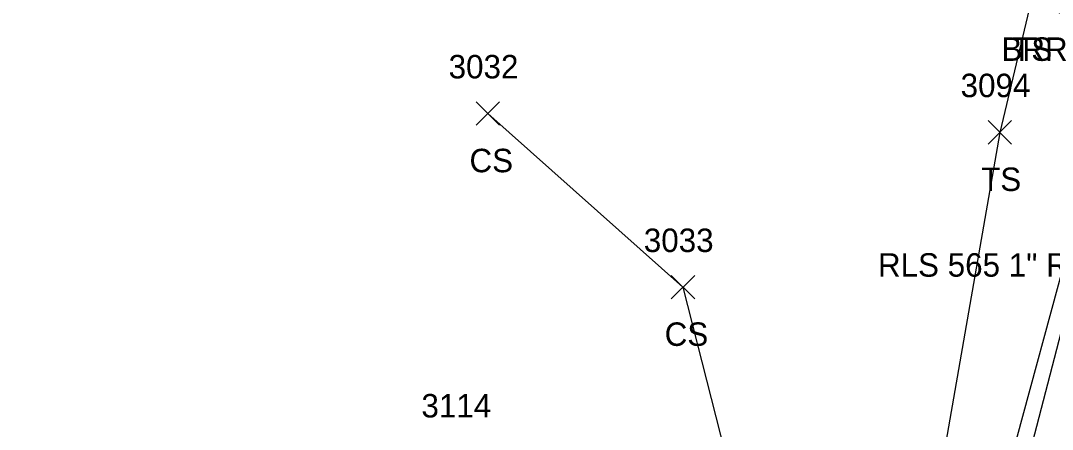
# Model space of a CAD drawing. Extents: x 1462089 to 1464015, y 730534 to 736144.
# Drawn here: x 1463000.8 to 1463088.7, y 733149.9 to 733184.7 of the extents above; entities that cross this region are included whole.
import ezdxf

# ---------------------------------------------------------------- set-up
doc = ezdxf.new("R2010")
doc.units = 0
for name, color, linetype in [('L_A', 7, 'Continuous'), ('L_I', 7, 'Continuous'), ('L_TIC', 7, 'Continuous'), ('LABL', 7, 'Continuous'), ('LARO', 7, 'Continuous'), ('LELB', 7, 'Continuous'), ('M_C', 7, 'Continuous')]:
    doc.layers.add(name, color=color, linetype=linetype)

msp = doc.modelspace()

# ---------------------------------------------------------------- linework, layer by layer
at = {"layer": 'L_TIC'}
for points in [[(1463039.617, 733175.806), (1463041.617, 733177.806)], [(1463041.617, 733175.806), (1463039.617, 733177.806)], [(1463083.26, 733174.207), (1463085.26, 733176.207)], [(1463085.26, 733174.207), (1463083.26, 733176.207)], [(1463056.254, 733161.004), (1463058.254, 733163.004)], [(1463058.254, 733161.004), (1463056.254, 733163.004)]]:
    msp.add_lwpolyline(points, dxfattribs=at)
at = {"layer": 'LABL'}
msp.add_lwpolyline([(1463052.447, 733194.496), (1463067.072, 733192.93), (1463078.582, 733189.909), (1463086.907, 733186.301), (1463094.259, 733183.581), (1463092.108, 733172.762), (1463083.334, 733140.42), (1463080.341, 733131.515), (1463076.284, 733126.395), (1463067.395, 733109.858), (1463045.394, 733071.47), (1463024.958, 733052.891)], dxfattribs=at)
at = {"layer": 'LARO'}
msp.add_lwpolyline([(1463094.762, 733228.152), (1463096.033, 733229.515), (1463107.108, 733225.669), (1463106.44, 733220.787), (1463101.841, 733210.568), (1463094.259, 733183.581), (1463093.234, 733172.664), (1463084.959, 733140.715), (1463082.497, 733130.849), (1463075.102, 733107.4), (1463060.706, 733062.181), (1463041.425, 733003.632), (1463027.295, 732956.249), (1463020.696, 732939.68), (1463009.719, 732922.589), (1463000.799, 732913.835)], dxfattribs=at)
at = {"layer": 'LELB'}
for points in [[(1463067.072, 733192.93), (1463070.426, 733198.242), (1463078.663, 733227.75), (1463094.762, 733228.152), (1463099.993, 733222.403), (1463095.741, 733212.266), (1463086.907, 733186.301), (1463084.26, 733175.207), (1463078.193, 733140.321), (1463061.256, 733133.548), (1463056.171, 733129.908), (1463054.782, 733128.225), (1463056.002, 733122.823), (1463058.279, 733122.507), (1463065.523, 733123.029), (1463076.284, 733126.395), (1463069.526, 733109.401), (1463055.631, 733063.213), (1463034.634, 733001.948)], [(1463040.617, 733176.806), (1463057.254, 733162.004), (1463062.073, 733143.026), (1463061.256, 733133.548), (1463056.726, 733129.289)]]:
    msp.add_lwpolyline(points, dxfattribs=at)

# ---------------------------------------------------------------- texts
at = {"layer": 'L_A'}
for s, p in [('BRR', (1463084.395, 733181.301)), ('TS', (1463085.316, 733181.301)), ('CS', (1463039.058, 733171.806)), ('TS', (1463082.669, 733170.207)), ('CS', (1463055.695, 733157.004))]:
    msp.add_text(s, height=2, dxfattribs=at).set_placement(p)
at = {"layer": 'L_I'}
for s, p in [('3032', (1463037.279, 733179.806)), ('3094', (1463080.921, 733178.207)), ('3033', (1463053.916, 733165.004)), ('3114', (1463034.961, 733150.901)), ('3114', (1463034.961, 733150.901))]:
    msp.add_text(s, height=2, dxfattribs=at).set_placement(p)
at = {"layer": 'M_C'}
msp.add_text('RLS 565 1" REBAR FLUSH', height=2, dxfattribs=at).set_placement((1463073.874, 733162.903))

doc.saveas('drawing.dxf')
